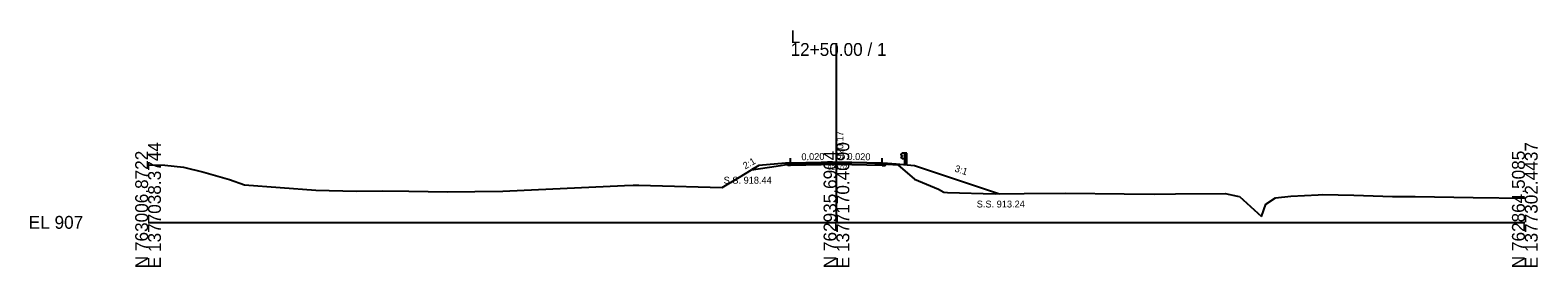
# Model space of a CAD drawing. Extents: x -26 to 303, y -10 to 6523.
# Drawn here: x -25.7 to 302.8, y 2490.3 to 2541.9 of the extents above; entities that cross this region are included whole.
import ezdxf

# ---------------------------------------------------------------- set-up
doc = ezdxf.new("R2010")
doc.units = 0
for name, color, linetype in [('Exist Cross Section Cell', 7, 'Continuous'), ('Exist XS Center Line Elevation Label', 7, 'Continuous'), ('Exist XS Ground Line', 7, 'Continuous'), ('Prop XS Dump Level', 7, 'Continuous'), ('Prop XS Elevation Labels', 7, 'Continuous'), ('Prop XS EOT Tick Mark', 7, 'Continuous'), ('Prop XS Finish Grade', 7, 'Continuous'), ('Prop XS Finish Grade Earthwork', 7, 'Continuous'), ('Prop XS Finish Grade Pavement', 7, 'Continuous'), ('Prop XS Guardrail', 7, 'Continuous'), ('Prop XS Pvmt Edge Slope', 7, 'Continuous'), ('Prop XS SE Text', 7, 'Continuous'), ('Prop XS Side Slope Text', 7, 'Continuous'), ('Prop XS SS Elevation Text', 7, 'Continuous'), ('Prop XS Subgrade Earthwork', 7, 'Continuous')]:
    doc.layers.add(name, color=color, linetype=linetype)

msp = doc.modelspace()

# ---------------------------------------------------------------- linework, layer by layer
at = {"layer": 'Exist Cross Section Cell'}
for p, q in [((150, 2500), (150, 2539.07)), ((0, 2500), (150, 2500)), ((150, 2500), (300, 2500))]:
    msp.add_line(p, q, dxfattribs=at)
at = {"layer": 'Exist XS Ground Line'}
for p, q in [((0, 2512.52), (3.63, 2512.43)), ((3.63, 2512.43), (7.69, 2512.02)), ((7.69, 2512.02), (12.15, 2510.93)), ((12.15, 2510.93), (17.73, 2509.33)), ((128.89, 2509.82), (131.48, 2511.44)), ((131.48, 2511.44), (136.85, 2512.24)), ((136.85, 2512.24), (140.05, 2512.74)), ((140.05, 2512.74), (141.33, 2512.78)), ((141.33, 2512.78), (149.11, 2513.02)), ((149.11, 2513.02), (150, 2513.02)), ((150, 2513.02), (156.63, 2512.95)), ((156.63, 2512.95), (157.8, 2512.94)), ((157.8, 2512.94), (158.85, 2512.82)), ((158.85, 2512.82), (163.41, 2512.51)), ((163.41, 2512.51), (167, 2509.41)), ((17.73, 2509.33), (20.98, 2508.2)), ((20.98, 2508.2), (36.56, 2507.02)), ((36.56, 2507.02), (45.37, 2506.77)), ((45.37, 2506.77), (51.07, 2506.86)), ((51.07, 2506.86), (56.82, 2506.77)), ((56.82, 2506.77), (65.22, 2506.64)), ((71.2, 2506.7), (77.31, 2506.82)), ((77.31, 2506.82), (103.85, 2508.01)), ((103.85, 2508.01), (105.72, 2508.09)), ((105.72, 2508.09), (106.95, 2508.12)), ((106.95, 2508.12), (109.46, 2508.04)), ((109.46, 2508.04), (125.12, 2507.61)), ((125.12, 2507.61), (128.89, 2509.82)), ((167, 2509.41), (172.26, 2507.21)), ((172.26, 2507.21), (173.39, 2506.55)), ((65.22, 2506.64), (71.2, 2506.7)), ((173.39, 2506.55), (174.23, 2506.54)), ((174.23, 2506.54), (184.56, 2506.23)), ((184.56, 2506.23), (190.92, 2506.32)), ((190.92, 2506.32), (199.98, 2506.37)), ((199.98, 2506.37), (212.68, 2506.19)), ((212.68, 2506.19), (219.28, 2506.13)), ((219.28, 2506.13), (223.88, 2506.19)), ((223.88, 2506.19), (234.69, 2506.26)), ((234.69, 2506.26), (237.38, 2505.71)), ((237.38, 2505.71), (237.86, 2505.61)), ((237.86, 2505.61), (242.6, 2501.27)), ((242.6, 2501.27), (243.58, 2503.98)), ((243.58, 2503.98), (245.69, 2505.32)), ((245.69, 2505.32), (249, 2505.7)), ((249, 2505.7), (254.96, 2505.99)), ((254.96, 2505.99), (255.91, 2506.1)), ((255.91, 2506.1), (262.73, 2505.91)), ((262.73, 2505.91), (271.16, 2505.65)), ((271.16, 2505.65), (276.13, 2505.66)), ((276.13, 2505.66), (288.72, 2505.41)), ((288.72, 2505.41), (300, 2505.24))]:
    msp.add_line(p, q, dxfattribs=at)
at = {"layer": 'Prop XS Dump Level'}
for p, q in [((140, 2512.97), (150, 2513.17)), ((150, 2513.17), (160, 2512.97))]:
    msp.add_line(p, q, dxfattribs=at)
at = {"layer": 'Prop XS EOT Tick Mark'}
for p, q in [((140, 2512.97), (140, 2513.97)), ((160, 2512.97), (160, 2513.97))]:
    msp.add_line(p, q, dxfattribs=at)
at = {"layer": 'Prop XS Finish Grade'}
for p, q in [((140, 2512.97), (138.9, 2512.88)), ((160, 2512.97), (161.1, 2512.88))]:
    msp.add_line(p, q, dxfattribs=at)
at = {"layer": 'Prop XS Finish Grade Earthwork'}
for p, q in [((133.06, 2512.42), (131.48, 2511.44)), ((138.9, 2512.88), (133.06, 2512.42)), ((161.1, 2512.88), (163, 2512.73)), ((163, 2512.73), (167, 2512.41)), ((167, 2512.41), (185.51, 2506.24))]:
    msp.add_line(p, q, dxfattribs=at)
at = {"layer": 'Prop XS Finish Grade Pavement'}
for p, q in [((140, 2512.97), (150, 2513.17)), ((150, 2513.17), (160, 2512.97))]:
    msp.add_line(p, q, dxfattribs=at)
at = {"layer": 'Prop XS Guardrail'}
for p, q in [((164.03, 2514.85), (164, 2514.79)), ((164, 2514.79), (164.03, 2514.73)), ((164.03, 2514.23), (164, 2514.17)), ((164, 2514.17), (164.03, 2514.11)), ((164.32, 2515.05), (164.03, 2514.85)), ((164.03, 2514.73), (164.32, 2514.53)), ((164.32, 2514.43), (164.03, 2514.23)), ((164.03, 2514.11), (164.32, 2513.91)), ((164.82, 2515.05), (164.32, 2515.05)), ((164.32, 2514.53), (164.32, 2514.43)), ((164.32, 2513.91), (164.82, 2513.91)), ((165.32, 2515.05), (164.82, 2515.05)), ((164.82, 2515.05), (164.82, 2512.55)), ((165.32, 2512.55), (165.32, 2515.05))]:
    msp.add_line(p, q, dxfattribs=at)
at = {"layer": 'Prop XS Pvmt Edge Slope'}
for p, q in [((140, 2512.97), (139.4, 2512.38)), ((160, 2512.97), (160.6, 2512.38))]:
    msp.add_line(p, q, dxfattribs=at)
at = {"layer": 'Prop XS Subgrade Earthwork'}
for p, q in [((139.4, 2512.38), (138.9, 2512.88)), ((140, 2512.39), (139.4, 2512.38)), ((150, 2512.59), (140, 2512.39)), ((160, 2512.39), (150, 2512.59)), ((160, 2512.39), (160.6, 2512.38)), ((160.6, 2512.38), (161.1, 2512.88))]:
    msp.add_line(p, q, dxfattribs=at)

# ---------------------------------------------------------------- texts
at = {"layer": 'Exist Cross Section Cell'}
for s, p in [('L', (140, 2539.07)), ('12+50.00 / 1', (140, 2536.27)), ('EL 907', (-26, 2498.6))]:
    msp.add_text(s, height=2.8, dxfattribs=at).set_placement(p)
for s, p in [('E 1377038.3744', (2.8, 2490)), ('E 1377170.4090', (152.8, 2490)), ('E 1377302.4437', (302.8, 2490)), ('N 763006.8722', (0, 2490)), ('N 762935.6904', (150, 2490)), ('N 762864.5085', (300, 2490))]:
    msp.add_text(s, height=2.8, rotation=90, dxfattribs=at).set_placement(p)
at = {"layer": 'Exist XS Center Line Elevation Label'}
msp.add_text('920.02', height=0.998, dxfattribs=at).set_placement((148.15, 2511.44))
at = {"layer": 'Prop XS Dump Level'}
for p in [(137, 2512.69), (163, 2512.69)]:
    msp.add_text('Case1', height=0.04, dxfattribs=at).set_placement(p)
at = {"layer": 'Prop XS Elevation Labels'}
msp.add_text(' 920.17', height=1.5, rotation=90, dxfattribs=at).set_placement((151.5, 2513.17))
at = {"layer": 'Prop XS SE Text'}
for rotation, p in [(1.1458, (142.38, 2513.52)), (358.8542, (152.38, 2513.62))]:
    msp.add_text('0.020', height=1.5, rotation=rotation, dxfattribs=at).set_placement(p)
at = {"layer": 'Prop XS Side Slope Text'}
for s, rotation, p in [('2:1', 29.8214, (130.14, 2511.52)), ('3:1', 341.5651, (175.64, 2511.11))]:
    msp.add_text(s, height=1.5, rotation=rotation, dxfattribs=at).set_placement(p)
at = {"layer": 'Prop XS SS Elevation Text'}
for s, p in [('S.S. 918.44', (125.42, 2508.43)), ('S.S. 913.24', (180.57, 2503.24))]:
    msp.add_text(s, height=1.5, dxfattribs=at).set_placement(p)

doc.saveas('drawing.dxf')
